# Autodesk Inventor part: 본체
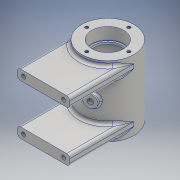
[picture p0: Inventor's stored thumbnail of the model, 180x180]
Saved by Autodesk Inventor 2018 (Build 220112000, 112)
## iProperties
Created: 2020-07
Part Number: 본체
Material: 알루미늄 6061
Document SubType Name: Modeling
Designer: home
Density: 2.7 g/cm^3
Appearance: 알루미늄 - 평지
Mass: 305.802 g
Surface Area: 360.882 cm^2
Volume: 113.26 cm^3
Author: home
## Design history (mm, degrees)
sketch "스케치1"
  geometry: L1 (0, 54.042)-(0, -37.312); L2 (16, 35)-(16, 23); L3 (16, 23)-(14, 23); L4 (14, 23)-(14, 21); L5 (14, 21)-(21, 21); L6 (21, 21)-(21, -21); L7 (21, -21)-(14, -21); L8 (14, -21)-(14, -23); L9 (16, -35)-(26, -35); L10 (26, -35)-(26, 35); L11 (26, 35)-(16, 35); L12 (14, -23)-(16, -23); L13 (16, -23)-(16, -35); 1 further point
  constraints: 26 end point, 8 perpendicular, 4 point on line, 2 vertical, 1 horizontal
  dimensions: "d0" = 52 diameter of L10 L1; "d1" = 32 diameter of L13 L1; "d2" = 42 diameter of L6 L1; "d3" = 28 diameter of L8 L1; "d7" = 12 distance of L2.start L2.end; "d8" = 12 distance of L12.end L9.start; "d9" = 70 distance of L9.end L10.end; "d10" = 35 vertical distance of point (0, 0) L10.end; "d12" = 42 distance of L5.end L6.end; "d13" = 2 distance of L3.end L4.end; "d15" = 19.04172 distance from line of L1.start L11; "d16" = 72.31179 distance from line of L1.end L11
revolve "회전1" sketch "스케치1" stored, may be unused: angle "d14" = 90 deg
node "작업 평면1"
sketch "스케치2"
  geometry: L1 (-26, 30)-(26, 30); L2 (26, 30)-(26, 20); L3 (26, 20)-(-26, 20); L4 (-26, 20)-(-26, 30); L5 (-26, -20)-(26, -20); L6 (26, -20)-(26, -30); L7 (26, -30)-(-26, -30); L8 (-26, -30)-(-26, -20); 1 further point
  constraints: 16 end point, 4 parallel, 2 horizontal, 2 perpendicular
  dimensions: "d18" = 10 distance of L3.end L1.start; "d21" = 10 distance of L7.end L5.start; "d24" = 30 distance from line of L1 point (0, 0); "d25" = 30 distance from line of L7 point (0, 0); "d28" = 52 distance of L1.start L1.end; "d29" = 52 distance of L6.end L7.end; "d30" = 26 distance from line of point (0, 0) L4; "d31" = 26 distance from line of L8 point (0, 0)
extrude "돌출1" join sketch "스케치2" stored distance "d26" = 10; taper "d27" = 0 deg
sketch "스케치3"
  geometry: L1 (26, 30)-(-26, 30) reference; 3 further points
  constraints: 1 horizontal alignment
  dimensions: "d32" = 5 distance from line of L1 point (20, 25); "d33" = 20 horizontal distance of point (0, 0) point (20, 25); "d35" = 20 horizontal distance of point (0, 0) point (-20, 25)
hole "구멍1" sketch "스케치3" at (20, 25), (-20, 25) diameter "d36" = 4.134; stored, may be unused: countersink angle "d40" = 90 deg, drill point angle "d42" = 118 deg; dims "d37" = 8, "d38" = 4, "d39" = 2, "d41" = 10
node "작업 평면2"
sketch "스케치4"
  geometry: C1 r 5 at (0, 0); 1 further point
  constraints: 1 centre point, 1 coincident
  dimensions: "d44" = 10 diameter of C1
extrude "돌출2" join sketch "스케치4" stored distance "d45" = 10; taper "d46" = 0 deg
sketch "스케치5"
  geometry: C1 r 5 at (0, 0) reference; 1 further point
hole "구멍2" sketch "스케치5" at (0, 0) diameter "d50" = 5.188; stored, may be unused: countersink angle "d54" = 90 deg, drill point angle "d56" = 118 deg; dims "d51" = 12, "d52" = 4, "d53" = 2, "d55" = 16
sketch "스케치6"
  geometry: C1 r 2.594 at (0, 0) reference; C2 r 6 at (0, 0); 1 further point
  constraints: 1 centre point, 1 coincident
  dimensions: "d60" = 12 diameter of C2
extrude "돌출3" join sketch "스케치6" stored distance "d61" = 10; taper "d62" = 0 deg
sketch "스케치7"
  geometry: 2 further points
  constraints: 1 vertical alignment
  dimensions: "d63" = 21 distance of point (0, 0) point (0, 21)
hole "구멍3" sketch "스케치7" at (0, 21) diameter "d64" = 3.242; stored, may be unused: countersink angle "d68" = 90 deg, drill point angle "d70" = 118 deg; dims "d65" = 8, "d66" = 4, "d67" = 2, "d69" = 10
sketch "스케치8"
  geometry: L1 (-5, 90)-(-5, 38) reference; L2 (65, 90)-(-5, 90) reference; 2 further points
  constraints: 1 other
  dimensions: "d74" = 35 distance from line of L1 point (30, 66); "d75" = 24 distance from line of L2 point (30, 66)
feature "엠보싱1" sketch "스케치8" dims "d0" = 52, "d1" = 32, "d2" = 42, "d3" = 28, "d7" = 12, "d8" = 12, "d9" = 70, "d10" = 35, "d12" = 42, "d13" = 2, "d15" = 19.04172, "d16" = 72.31179, "d76" = 0.5, "d77" = 0
fillet "모깎기1" dims "d78" = 0.3, "d79" = 3, "d80" = 2
fillet "모깎기2" dims "d81" = 2
node "솔리드1"
mirror "미러1"
pattern_circular "원형 패턴2" dims angle "d58" = 160 deg
pattern_circular "원형 패턴3" dims angle "d72" = 360 deg
mirror "미러2"
other parameters: "d17" = -64, "d43" = 29
